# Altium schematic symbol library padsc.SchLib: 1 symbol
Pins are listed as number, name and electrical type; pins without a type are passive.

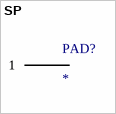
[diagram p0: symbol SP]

## SP
designator PAD?
Solder pad
footprint PCBComponent_1
pins: Pad 1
